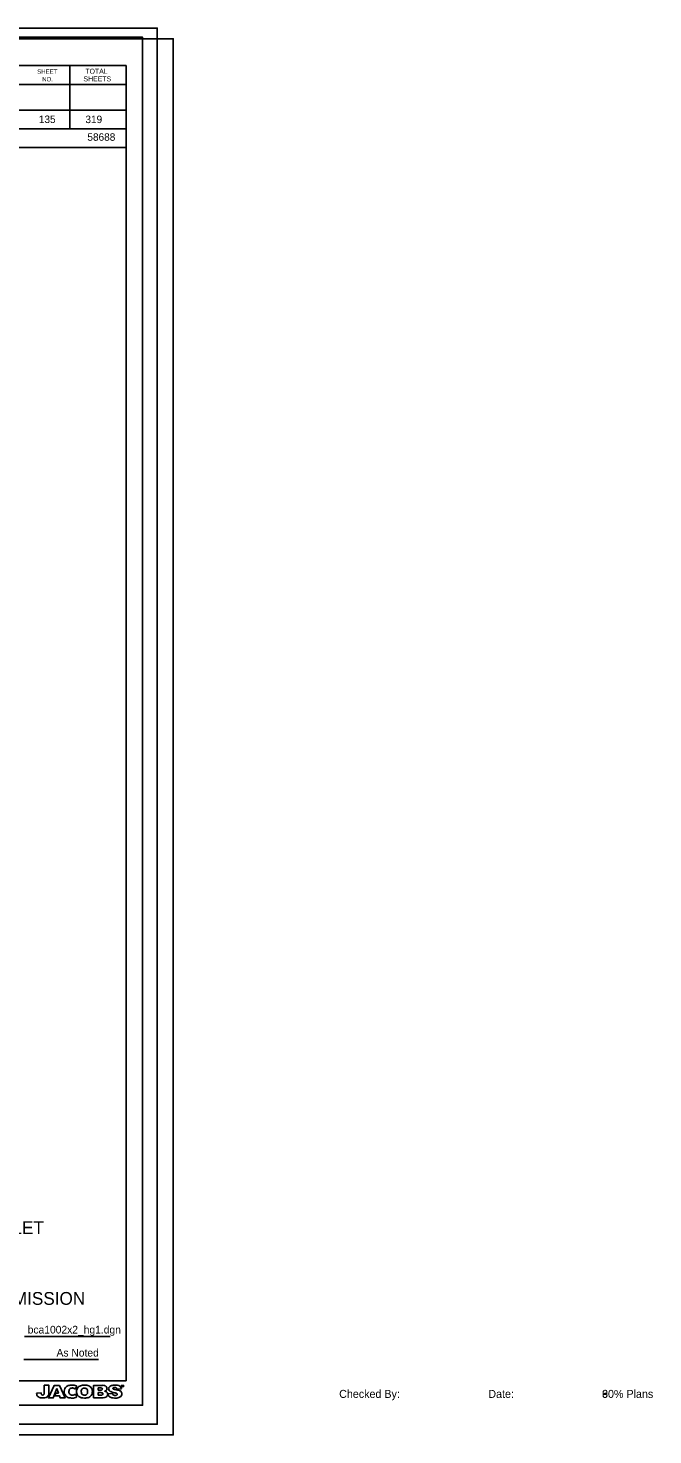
# Model space of a CAD drawing. Extents: x -1063117.9 to -1063075.9, y -253323.6 to -253301.6.
# Drawn here: x -1063085.67 to -1063075.92, y -253323.61 to -253301.63 of the extents above; entities that cross this region are included whole.
import ezdxf

# ---------------------------------------------------------------- set-up
doc = ezdxf.new("R2010")
doc.units = 0
for name, color, linetype in [('30% Plans', 7, 'Continuous'), ('60% Plans', 7, 'Continuous'), ('90% Plans', 7, 'Continuous'), ('border', 7, 'Continuous'), ('Border 2660-Hwy18 - Level 62', 7, 'Continuous'), ('Border 2660-Hwy18 - Level 63', 7, 'Continuous'), ('Border 2660-Hwy18 - Text', 7, 'Continuous'), ('Border 2660-Hwy18 - Title Text', 7, 'Continuous'), ('Level 62 PDF', 7, 'Continuous'), ('Text', 7, 'Continuous'), ('Title Block Text', 7, 'Continuous'), ('Title Text', 7, 'Continuous')]:
    doc.layers.add(name, color=color, linetype=linetype)

msp = doc.modelspace()

# ---------------------------------------------------------------- linework, layer by layer
at = {"layer": 'border'}
for p, q in [((-1063116.157, -253302.216), (-1063084.146, -253302.216)), ((-1063085.026, -253302.216), (-1063085.026, -253303.204)), ((-1063084.146, -253322.761), (-1063084.146, -253302.216)), ((-1063084.146, -253302.51), (-1063088.456, -253302.51)), ((-1063084.146, -253302.508), (-1063084.146, -253302.508)), ((-1063084.146, -253302.91), (-1063088.456, -253302.91)), ((-1063088.16, -253302.91), (-1063084.146, -253302.91)), ((-1063084.146, -253303.204), (-1063092.372, -253303.204)), ((-1063088.456, -253303.495), (-1063084.146, -253303.495)), ((-1063085.73, -253322.071), (-1063084.394, -253322.071)), ((-1063085.742, -253322.431), (-1063084.577, -253322.431)), ((-1063084.146, -253322.761), (-1063116.157, -253322.761))]:
    msp.add_line(p, q, dxfattribs=at)
for points in [[(-1063085.351, -253322.941), (-1063085.351, -253322.831), (-1063085.425, -253322.831), (-1063085.425, -253322.951)], [(-1063085.228, -253322.883), (-1063085.202, -253322.954), (-1063085.241, -253322.954), (-1063085.257, -253322.996), (-1063085.187, -253322.996), (-1063085.175, -253323.029), (-1063085.098, -253323.029), (-1063085.187, -253322.833), (-1063085.268, -253322.833), (-1063085.358, -253323.029), (-1063085.282, -253323.029), (-1063085.228, -253322.883)], [(-1063084.512, -253322.833), (-1063084.654, -253322.833), (-1063084.654, -253323.029)], [(-1063084.547, -253322.872), (-1063084.58, -253322.872), (-1063084.58, -253322.909)], [(-1063084.207, -253322.835), (-1063084.222, -253322.835), (-1063084.222, -253322.837), (-1063084.216, -253322.837), (-1063084.216, -253322.854), (-1063084.214, -253322.854), (-1063084.214, -253322.837), (-1063084.207, -253322.837), (-1063084.207, -253322.835)], [(-1063084.203, -253322.838), (-1063084.203, -253322.838), (-1063084.197, -253322.854), (-1063084.195, -253322.854), (-1063084.189, -253322.838), (-1063084.189, -253322.838), (-1063084.189, -253322.854), (-1063084.186, -253322.854), (-1063084.186, -253322.835), (-1063084.19, -253322.835), (-1063084.196, -253322.851), (-1063084.202, -253322.835), (-1063084.205, -253322.835), (-1063084.205, -253322.854), (-1063084.203, -253322.854), (-1063084.203, -253322.838)], [(-1063085.473, -253322.952), (-1063085.543, -253322.956)], [(-1063084.654, -253323.029), (-1063084.526, -253323.029)], [(-1063084.58, -253322.909), (-1063084.545, -253322.909)], [(-1063084.542, -253322.947), (-1063084.58, -253322.947), (-1063084.58, -253322.987)], [(-1063084.58, -253322.987), (-1063084.542, -253322.987)], [(-1063084.358, -253322.96), (-1063084.428, -253322.964)], [(-1063084.289, -253322.891), (-1063084.219, -253322.888)]]:
    msp.add_lwpolyline(points, dxfattribs=at)
for centre, radius, start, end in [((-1063085.013, -253322.926), 0.0987, 155.2444, 178.6811), ((-1063085.029, -253322.918), 0.0809, 126.8513, 155.2444), ((-1063085.009, -253322.944), 0.114, 94.7853, 126.8513), ((-1063084.988, -253322.93), 0.0556, 110.7655, 134.3139), ((-1063084.989, -253323.193), 0.363, 86.903, 94.7853), ((-1063084.989, -253322.928), 0.0529, 91.5073, 110.7655), ((-1063084.987, -253322.99), 0.116, 82.6359, 91.5073), ((-1063084.979, -253322.924), 0.0493, 65.5548, 82.6359), ((-1063084.975, -253322.943), 0.113, 56.9246, 86.903), ((-1063085.007, -253322.988), 0.119, 54.6002, 65.5548), ((-1063084.689, -253323.008), 0.276, 144.635, 154.8844), ((-1063084.82, -253322.928), 0.1, 148.6249, 181.2859), ((-1063084.841, -253322.915), 0.0755, 123.8806, 148.6249), ((-1063084.804, -253322.971), 0.142, 111.7104, 123.8806), ((-1063084.816, -253322.94), 0.109, 96.5371, 111.7104), ((-1063084.798, -253322.926), 0.0518, 117.7176, 136.1177), ((-1063084.785, -253323.213), 0.384, 91.9058, 96.5371), ((-1063084.804, -253322.914), 0.0382, 100.2108, 117.7176), ((-1063084.795, -253322.965), 0.0895, 90.9675, 100.2108), ((-1063084.791, -253322.995), 0.166, 73.4477, 92.4253), ((-1063084.796, -253322.937), 0.0622, 67.077, 90.4218), ((-1063084.787, -253322.916), 0.0386, 24.6274, 67.077), ((-1063084.775, -253322.943), 0.112, 41.1934, 73.4477), ((-1063084.735, -253322.908), 0.0579, 18.6966, 41.1934), ((-1063084.549, -253323.007), 0.135, 86.2098, 89.3498), ((-1063084.543, -253322.924), 0.0514, 74.8723, 86.2098), ((-1063084.535, -253322.893), 0.0196, 40.2425, 74.8723), ((-1063084.528, -253322.887), 0.0108, 21.9604, 40.2425), ((-1063084.536, -253322.891), 0.0195, 341.4625, 21.9604), ((-1063084.512, -253322.936), 0.104, 72.1885, 90.1477), ((-1063084.499, -253322.895), 0.0603, 61.4844, 72.1885), ((-1063084.497, -253322.892), 0.0564, 34.7868, 61.4844), ((-1063084.476, -253322.877), 0.0315, 16.9455, 34.7868), ((-1063084.49, -253322.881), 0.0455, 347.0949, 16.9455), ((-1063084.372, -253322.888), 0.0476, 124.08, 177.6485), ((-1063084.378, -253322.887), 0.0416, 177.6485, 218.8535), ((-1063084.341, -253322.934), 0.103, 108.2808, 124.08), ((-1063084.347, -253322.913), 0.0811, 99.8173, 108.2808), ((-1063084.32, -253323.072), 0.242, 93.402, 99.8173), ((-1063084.335, -253322.883), 0.016, 146.4706, 165.3108), ((-1063084.343, -253322.881), 0.00815, 165.3108, 208.2887), ((-1063084.336, -253322.876), 0.0169, 211.7417, 226.6339), ((-1063084.341, -253322.879), 0.00877, 130.7855, 146.4706), ((-1063084.331, -253322.892), 0.0256, 97.3055, 130.7855), ((-1063084.319, -253323.083), 0.254, 80.6549, 93.402), ((-1063084.325, -253322.935), 0.0692, 81.3212, 97.3055), ((-1063084.32, -253322.902), 0.0359, 57.474, 81.3212), ((-1063084.312, -253322.889), 0.0202, 37.1977, 57.474), ((-1063084.323, -253322.898), 0.0351, 11.0051, 37.1977), ((-1063084.293, -253322.921), 0.0897, 57.5906, 80.6549), ((-1063084.271, -253322.887), 0.0494, 39.0736, 57.5906), ((-1063084.28, -253322.895), 0.0612, 6.4385, 39.0736), ((-1063085.421, -253322.946), 0.123, 184.5698, 198.1069), ((-1063085.488, -253322.968), 0.0527, 198.1069, 225.9799), ((-1063085.469, -253322.949), 0.0797, 225.9799, 261.0714), ((-1063085.444, -253322.786), 0.244, 261.0714, 269.9405), ((-1063085.412, -253322.954), 0.0602, 178.2556, 191.4961), ((-1063085.444, -253322.961), 0.0277, 191.4961, 218.7511), ((-1063085.453, -253322.968), 0.0164, 218.7511, 257.488), ((-1063085.449, -253322.95), 0.0345, 257.488, 275.7834), ((-1063085.448, -253322.959), 0.0257, 275.7834, 301.6926), ((-1063085.444, -253322.863), 0.167, 269.9405, 279.1616), ((-1063085.441, -253322.97), 0.0122, 301.6926, 325.4171), ((-1063085.455, -253322.961), 0.0285, 325.4171, 349.1575), ((-1063085.504, -253322.952), 0.0792, 349.1575, 360), ((-1063085.432, -253322.936), 0.0931, 279.1616, 305.8646), ((-1063085.412, -253322.964), 0.0585, 305.8646, 338.7843), ((-1063085.406, -253322.966), 0.0527, 338.7843, 350.0951), ((-1063085.895, -253322.881), 0.549, 350.0951, 351.3706), ((-1063085.475, -253322.945), 0.124, 351.3706, 1.8291), ((-1063084.959, -253322.927), 0.153, 178.6811, 194.3912), ((-1063085.05, -253322.95), 0.0582, 194.3912, 214.1799), ((-1063084.994, -253322.912), 0.127, 214.1799, 231.6615), ((-1063085.025, -253322.951), 0.0765, 231.6616, 258.686), ((-1063084.981, -253322.734), 0.298, 258.686, 268.8163), ((-1063084.934, -253322.933), 0.104, 161.2834, 178.6702), ((-1063084.953, -253322.933), 0.0855, 178.6702, 195.8531), ((-1063084.994, -253322.945), 0.0421, 195.8531, 214.5369), ((-1063085.01, -253322.908), 0.0243, 134.3139, 161.2834), ((-1063084.997, -253322.946), 0.0388, 214.5369, 253.1918), ((-1063084.986, -253322.91), 0.0769, 253.1918, 291.1956), ((-1063084.985, -253322.886), 0.146, 268.8163, 299.3878), ((-1063084.992, -253322.895), 0.0928, 291.1956, 305.5144), ((-1063084.575, -253322.788), 0.407, 206.7197, 213.678), ((-1063084.768, -253322.927), 0.152, 181.2859, 193.1956), ((-1063084.85, -253322.946), 0.0683, 193.1956, 217.7499), ((-1063084.816, -253322.92), 0.111, 217.7499, 244.1703), ((-1063084.827, -253322.943), 0.0859, 244.1703, 259.4942), ((-1063084.755, -253322.931), 0.0917, 160.8611, 181.2981), ((-1063084.751, -253322.931), 0.0951, 181.2981, 197.9492), ((-1063084.788, -253322.733), 0.299, 259.4942, 268.6426), ((-1063084.814, -253322.91), 0.0287, 136.1177, 160.8611), ((-1063084.814, -253322.951), 0.0299, 197.9492, 222.7741), ((-1063084.801, -253322.939), 0.0474, 222.7741, 250.1955), ((-1063084.8, -253322.936), 0.0507, 250.1955, 269.1264), ((-1063084.797, -253322.795), 0.191, 269.1264, 272.0424), ((-1063084.791, -253322.852), 0.18, 268.6426, 285.9017), ((-1063084.792, -253322.935), 0.0512, 272.0424, 299.5401), ((-1063084.785, -253322.949), 0.036, 299.5401, 342.4003), ((-1063084.803, -253322.923), 0.056, 2.7442, 24.6274), ((-1063084.837, -253322.932), 0.091, 342.4003, 0.0845), ((-1063084.996, -253322.932), 0.249, 0.0845, 2.7442), ((-1063084.769, -253322.929), 0.101, 285.9017, 322.6714), ((-1063084.745, -253322.947), 0.0698, 322.6714, 344.5708), ((-1063084.803, -253322.931), 0.13, 344.5708, 18.6966), ((-1063084.545, -253322.846), 0.0633, 270.0363, 284.1438), ((-1063084.547, -253323.194), 0.247, 86.6838, 88.8756), ((-1063084.542, -253322.883), 0.104, 270.0001, 276.6749), ((-1063084.536, -253322.997), 0.0497, 75.9314, 86.6838), ((-1063084.535, -253322.888), 0.0196, 284.1438, 307.8865), ((-1063084.535, -253322.943), 0.043, 276.6749, 293.0645), ((-1063084.537, -253322.691), 0.338, 271.7224, 279.6279), ((-1063084.532, -253322.892), 0.0149, 307.8866, 341.4625), ((-1063084.531, -253322.98), 0.0328, 59.6202, 75.9314), ((-1063084.525, -253322.966), 0.0178, 293.0645, 337.5037), ((-1063084.522, -253322.965), 0.015, 30.8341, 59.6202), ((-1063084.525, -253322.966), 0.0177, 337.5037, 30.8341), ((-1063084.502, -253322.851), 0.0753, 284.6785, 296.8411), ((-1063084.499, -253323.015), 0.092, 61.0815, 79.9242), ((-1063084.49, -253322.964), 0.0609, 279.6279, 313.6357), ((-1063084.489, -253322.877), 0.0471, 296.8412, 329.8182), ((-1063084.474, -253322.968), 0.039, 44.9773, 61.0815), ((-1063084.475, -253322.885), 0.0307, 329.8182, 347.0949), ((-1063084.484, -253322.971), 0.0511, 313.6357, 342.9845), ((-1063084.478, -253322.973), 0.0452, 342.9845, 44.9773), ((-1063084.052, -253322.911), 0.38, 187.9971, 189.0947), ((-1063084.378, -253322.963), 0.0503, 189.0947, 202.464), ((-1063084.343, -253322.949), 0.0881, 202.464, 215.8926), ((-1063084.364, -253322.964), 0.0621, 215.8926, 243.2968), ((-1063084.366, -253322.878), 0.0566, 218.8535, 233.6549), ((-1063084.352, -253322.859), 0.0797, 233.6549, 244.7689), ((-1063084.351, -253322.939), 0.0904, 243.2968, 257.4598), ((-1063084.32, -253322.79), 0.156, 244.7689, 253.473), ((-1063084.324, -253322.819), 0.213, 257.4598, 268.8656), ((-1063084.272, -253322.63), 0.323, 253.473, 259.8297), ((-1063084.306, -253322.952), 0.0523, 188.5141, 201.638), ((-1063084.325, -253322.96), 0.0319, 201.638, 242.3635), ((-1063084.338, -253322.878), 0.0145, 226.6339, 245.1429), ((-1063084.321, -253322.841), 0.0549, 245.1429, 260.9806), ((-1063084.319, -253322.948), 0.045, 242.3635, 264.6229), ((-1063084.404, -253323.369), 0.479, 77.5139, 80.9806), ((-1063084.382, -253323.24), 0.297, 76.0104, 79.8297), ((-1063084.317, -253322.451), 0.581, 268.8656, 270.7612), ((-1063084.316, -253322.913), 0.0806, 264.6229, 273.901), ((-1063084.334, -253323.047), 0.0974, 67.9593, 76.0104), ((-1063084.314, -253322.947), 0.0464, 273.901, 289.1925), ((-1063084.312, -253322.855), 0.177, 270.7612, 282.5001), ((-1063084.728, -253324.831), 1.977, 76.8035, 77.5139), ((-1063084.307, -253322.966), 0.0263, 289.1925, 322.566), ((-1063084.307, -253322.981), 0.0265, 39.9313, 67.9593), ((-1063084.298, -253322.973), 0.0145, 2.1813, 39.9313), ((-1063084.297, -253322.973), 0.0141, 322.566, 2.1813), ((-1063084.314, -253323.065), 0.163, 65.6998, 76.8035), ((-1063084.297, -253322.921), 0.109, 282.5001, 295.6144), ((-1063084.283, -253322.95), 0.0772, 295.6144, 314.022), ((-1063084.279, -253322.987), 0.0776, 51.3565, 65.6998), ((-1063084.263, -253322.967), 0.0523, 36.5162, 51.3565), ((-1063084.272, -253322.962), 0.0608, 314.022, 345.1611), ((-1063084.26, -253322.965), 0.0486, 345.1611, 36.5162)]:
    msp.add_arc(centre, radius, start, end, dxfattribs=at)
at = {"layer": 'Border 2660-Hwy18 - Level 62'}
msp.add_lwpolyline([(-1063117.777, -253301.63), (-1063083.659, -253301.63), (-1063083.659, -253323.44), (-1063117.777, -253323.44)], close=True, dxfattribs=at)
at = {"layer": 'Border 2660-Hwy18 - Level 63'}
msp.add_lwpolyline([(-1063117.888, -253301.773), (-1063083.889, -253301.773), (-1063083.889, -253323.143), (-1063117.888, -253323.143)], close=True, dxfattribs=at)
at = {"layer": 'Level 62 PDF'}
msp.add_lwpolyline([(-1063117.527, -253301.797), (-1063083.409, -253301.797), (-1063083.409, -253323.607), (-1063117.527, -253323.607)], close=True, dxfattribs=at)

# ---------------------------------------------------------------- texts
at = {"layer": '30% Plans'}
for s, p in [('Checked By:', (-1063080.82, -253323.029)), ('Date:', (-1063078.491, -253323.029)), ('30% Plans', (-1063076.716, -253323.029))]:
    msp.add_text(s, height=0.125, dxfattribs=at).set_placement(p)
at = {"layer": '60% Plans'}
for s, p in [('Checked By:', (-1063080.82, -253323.029)), ('Date:', (-1063078.491, -253323.029)), ('60% Plans', (-1063076.716, -253323.029))]:
    msp.add_text(s, height=0.125, dxfattribs=at).set_placement(p)
at = {"layer": '90% Plans'}
for s, p in [('Checked By:', (-1063080.82, -253323.029)), ('Date:', (-1063078.491, -253323.029)), ('90% Plans', (-1063076.716, -253323.029))]:
    msp.add_text(s, height=0.125, dxfattribs=at).set_placement(p)
at = {"layer": 'Border 2660-Hwy18 - Text'}
for s, height, p in [('SHEET', 0.0684, (-1063085.534, -253302.343)), ('NO.', 0.0684, (-1063085.456, -253302.462)), ('SHEETS', 0.0782, (-1063084.811, -253302.462)), ('TOTAL', 0.0782, (-1063084.782, -253302.343)), ('319', 0.1172, (-1063084.781, -253303.114))]:
    msp.add_text(s, height=height, dxfattribs=at).set_placement(p)
at = {"layer": 'Border 2660-Hwy18 - Title Text'}
msp.add_text('ARKANSAS STATE HIGHWAY COMMISSION', height=0.2, dxfattribs=at).set_placement((-1063090.357, -253321.575))
at = {"layer": 'Text'}
for s, height, p in [('135', 0.1172, (-1063085.508, -253303.113)), ('As Noted', 0.12, (-1063085.232, -253322.383))]:
    msp.add_text(s, height=height, dxfattribs=at).set_placement(p)
at = {"layer": 'Title Block Text'}
msp.add_text('bca1002x2_hg1.dgn', height=0.12, dxfattribs=at).set_placement((-1063085.682, -253322.023))
at = {"layer": 'Title Text'}
for s, height, p in [('58688', 0.1172, (-1063084.75, -253303.39)), ('HYDROGRAPH - BIG LAKE OUTLET', 0.2, (-1063089.932, -253320.47))]:
    msp.add_text(s, height=height, dxfattribs=at).set_placement(p)

doc.saveas('drawing.dxf')
